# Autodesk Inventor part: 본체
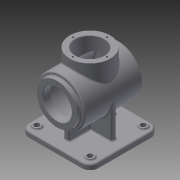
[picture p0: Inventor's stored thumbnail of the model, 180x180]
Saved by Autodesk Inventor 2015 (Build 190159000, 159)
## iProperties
Created: 2015-07
Part Number: 본체
Material: 일반
Document SubType Name: Modeling
Designer: PHO-1
Density: 1 g/cm^3
Appearance: 기본값
Author: PHO-1
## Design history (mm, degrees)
sketch "스케치1"
  geometry: L1 (-65, 65)-(65, 65); L2 (65, 65)-(65, -65); L3 (65, -65)-(-65, -65); L4 (-65, -65)-(-65, 65); 3 further points
  constraints: 8 end point, 2 midpoint, 2 parallel, 1 horizontal, 1 horizontal alignment, 1 perpendicular, 1 vertical alignment
  dimensions: "d0" = 130 distance of L1.start L1.end; "d1" = 130 distance of L3.end L1.start
extrude "돌출1" new body sketch "스케치1" distance "d2" = 10; taper "d3" = 0 deg
node "작업 평면1"
sketch "스케치4"
  geometry: C1 r 38 at (0, 0); 1 further point
  constraints: 1 centre point, 1 coincident
  dimensions: "d10" = 76 diameter of C1
extrude "돌출3" join sketch "스케치4" distance "d11" = 62; taper "d12" = 0 deg
sketch "스케치5"
  geometry: L1 (-45, 5)-(-45, -5); L2 (45, -5)-(45, 5); L3 (5, 45)-(-5, 45); L4 (-5, -45)-(5, -45); L5 (5, -45)-(5, -5); L6 (5, 5)-(5, 45); L7 (45, 5)-(5, 5); L8 (-5, 5)-(-45, 5); L9 (-5, 45)-(-5, 5); L10 (-5, -5)-(-5, -45); L11 (-45, -5)-(-5, -5); L12 (5, -5)-(45, -5); 5 further points
  constraints: 24 end point, 10 parallel, 4 perpendicular, 3 horizontal, 2 horizontal alignment, 2 midpoint, 2 vertical alignment
  dimensions: "d13" = 10 distance of L2.start L2.end; "d14" = 90 distance of L2.end L1.start; "d15" = 10 distance of L3.start L3.end; "d16" = 90 distance of L4.end L3.start
extrude "돌출4" join sketch "스케치5" distance "d17" = 68; taper "d18" = 0 deg
node "작업 평면2"
sketch "스케치7"
  geometry: C1 r 45 at (0, 78); 1 further point
  constraints: 1 centre point, 1 vertical alignment
  dimensions: "d20" = 78 distance of point (0, 0) C1.centre; "d21" = 90 diameter of C1
extrude "돌출5" join sketch "스케치7" distance "d22" = 110; taper "d23" = 0 deg
sketch "스케치8"
  geometry: C1 r 45 at (0, 0) reference; C2 r 38 at (0, 0); 1 further point
  constraints: 1 centre point, 1 coincident
  dimensions: "d24" = 76 diameter of C2
extrude "돌출6" join sketch "스케치8" distance "d25" = 7; taper "d26" = 0 deg
sketch "스케치9"
  geometry: L1 (-55, 33)-(-55, 123) reference; L2 (62, 40)-(62, 116) reference; L3 (-55, 78)-(62, 78); L4 (62, 105)-(48, 105); L5 (48, 105)-(48, 118); L6 (48, 118)-(-48, 118); L7 (-48, 118)-(-48, 78); 1 further point
  constraints: 10 end point, 4 perpendicular, 2 midpoint, 2 point on line
  dimensions: "d27" = 54 diameter of L4 L3; "d28" = 80 diameter of L6 L3; "d29" = 7 distance between parallel lines of L1 L7; "d30" = 96 distance of L5.end L6.end
revolve "회전1" sketch "스케치9" stored, may be unused: angle "d31" = 90 deg
sketch "스케치10"
  geometry: 2 further points
  constraints: 1 coincident
hole "구멍1" sketch "스케치10" at (0, 0) diameter "d32" = 54; stored, may be unused: countersink angle "d36" = 90 deg, drill point angle "d38" = 0 deg; dims "d33" = 6, "d34" = 4, "d35" = 2, "d37" = 8
sketch "스케치11" dims "d39" = 64
  geometry: C1 r 38 at (0, 0) reference; 3 further points
  constraints: 1 coincident, 1 horizontal alignment, 2 other
hole "구멍2" sketch "스케치11" at (32, 0) diameter "d40" = 3.242; stored, may be unused: countersink angle "d44" = 90 deg, drill point angle "d46" = 118 deg; dims "d41" = 8, "d42" = 4, "d43" = 2, "d45" = 10
sketch "스케치12" dims "d50" = 64
  geometry: 3 further points
  constraints: 1 coincident, 1 vertical alignment, 2 other
hole "구멍3" sketch "스케치12" at (0, 32) diameter "d51" = 3.242; stored, may be unused: countersink angle "d55" = 90 deg, drill point angle "d57" = 118 deg; dims "d52" = 8, "d53" = 4, "d54" = 2, "d56" = 10
sketch "스케치13"
  geometry: L1 (-50, 50)-(50, 50); L2 (50, 50)-(50, -50); L3 (50, -50)-(-50, -50); L4 (-50, -50)-(-50, 50); C1 r 7.5 at (-50, 50); C2 r 7.5 at (-50, -50); C3 r 7.5 at (50, 50); C4 r 7.5 at (50, -50); 3 further points
  constraints: 8 end point, 4 centre point, 4 coincident, 2 midpoint, 2 parallel, 1 horizontal, 1 horizontal alignment, 1 perpendicular, 1 vertical alignment
  dimensions: "d61" = 100 distance of L1.start L1.end; "d62" = 100 distance of L3.end L1.start; "d63" = 15 diameter of C1; "d64" = 15 diameter of C2; "d65" = 15 diameter of C4; "d66" = 15 diameter of C3
extrude "돌출7" join sketch "스케치13" distance "d67" = 3; taper "d68" = 0 deg
sketch "스케치14"
  geometry: C1 r 7.5 at (0, -100) reference; C2 r 7.5 at (-100, -100) reference; C3 r 7.5 at (-100, 0) reference; C4 r 7.5 at (0, 0) reference; 5 further points
  constraints: 4 coincident
hole "구멍4" sketch "스케치14" at (0, -100), (-100, -100), (0, 0), (-100, 0) diameter "d69" = 10; stored, may be unused: countersink angle "d73" = 90 deg, drill point angle "d75" = 118 deg; dims "d70" = 8, "d71" = 4, "d72" = 2, "d74" = 10
fillet "모깎기1" dims "d76" = 15
fillet "모깎기2" dims "d77" = 3
fillet "모깎기3" dims "d78" = 3
fillet "모깎기4" dims "d79" = 3
chamfer "모따기1" distance "d80" = 1; stored, may be unused: second distance "d81" = 2, angle "d82" = 45 deg
fillet "모깎기5" dims "d83" = 3
sketch "스케치15"
  geometry: C1 r 42 at (0, 0) reference; 2 further points
  constraints: 1 coincident, 1 other
feature "엠보싱1" sketch "스케치15" dims "d0" = 130, "d1" = 130, "d13" = 10, "d14" = 90, "d15" = 10, "d16" = 90, "d84" = 0.5, "d85" = 0
node "솔리드1"
pattern_circular "원형 패턴1" dims angle "d48" = 360 deg
pattern_circular "원형 패턴2" dims angle "d59" = 360 deg
node "투영된 루프1"
node "투영된 루프2"
node "투영된 루프3"
node "투영된 루프4"
node "투영된 루프5"
other parameters: "d9" = 78, "d19" = 55
